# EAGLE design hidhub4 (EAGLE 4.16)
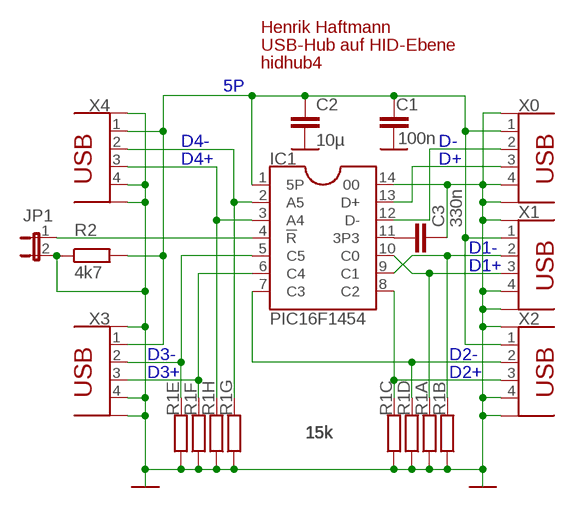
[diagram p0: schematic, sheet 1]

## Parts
C1  100n  C0805  [0805]
C2  10µ  C1206  [1206]
C3  330n  C1206  [1206]
IC1  PIC16F1454  PIC16F1454-I/P  [DIL14]
JP1  JP1E  [JP1]
R1A  15k  R0603  [0603]
R1B  15k  R0603  [0603]
R1C  15k  R0603  [0603]
R1D  15k  R0603  [0603]
R1E  15k  R0603  [0603]
R1F  15k  R0603  [0603]
R1G  15k  R0603  [0603]
R1H  15k  R0603  [0603]
R2  4k7  R0603  [0603]
X0  USBB  [USBB]
X1  USBA  [USBA]
X2  USBA  [USBA]
X3  USBA  [USBA]
X4  USBA  [USBA]

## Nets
3P3: C3.1 IC1.11(3P3)
5P: C1.1 C2.1 IC1.1(5P) R2.2 X0.1(UCC) X1.1(UCC) X2.1(UCC) X3.1(UCC) X4.1(UCC)
D1+: IC1.10(C0) R1A.2 X1.3(D+)
D1-: IC1.9(C1) R1B.2 X1.2(D-)
D2+: IC1.8(C2) R1C.2 X2.3(D+)
D2-: IC1.7(C3) R1D.2 X2.2(D-)
D3+: IC1.6(C4) R1F.2 X3.3(D+)
D3-: IC1.5(C5) R1E.2 X3.2(D-)
D4+: IC1.3(A4) R1H.2 X4.3(D+)
D4-: IC1.2(A5) R1G.2 X4.2(D-)
D+: IC1.13(D+) X0.3(D+)
D-: IC1.12(D-) X0.2(D-)
GND: C1.2 C2.2 C3.2 IC1.14 JP1.2 R1A.1 R1B.1 R1C.1 R1D.1 R1E.1 R1F.1 R1G.1 R1H.1 R2.1 X0.4(GND) X0.S1(S) X0.S2(S) X1.4(GND) X1.S1(S) X1.S2(S) X2.4(GND) X2.S1(S) X2.S2(S) X3.4(GND) X3.S1(S) X3.S2(S) X4.4(GND) X4.S1(S) X4.S2(S)
N$26: IC1.4(!R) JP1.1

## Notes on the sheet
- Henrik Haftmann
- USB-Hub auf HID-Ebene

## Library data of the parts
C1-C3 = fu:C: Kondensator
IC1 = hs-ul:PIC16F145*: 8-bit-Mikrocontroller mit USB Gezeichnet in Gehäuse-Anordnung, für USB-PCS500-Adapter. Typen: PIC16F1454 PIC16F1455 (mit ADU, DAU und 2x Analogvergleicher) Jeweils 8K x 14bit Flash, 1K RAM Features Benötigt keinen Quarz, interne PLL Benötigt keine USB-Serienwiderstände 3,3-V-Spannungsregler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
JP1 = jumper:JP1E: JUMPER
R1A R1B R1C R1D R1E R1F R1G R1H R2 = fu:R: Widerstand
X0 X1-X4 = km:USB: USB-Anschluss Buchse A oder B, mit Schirm

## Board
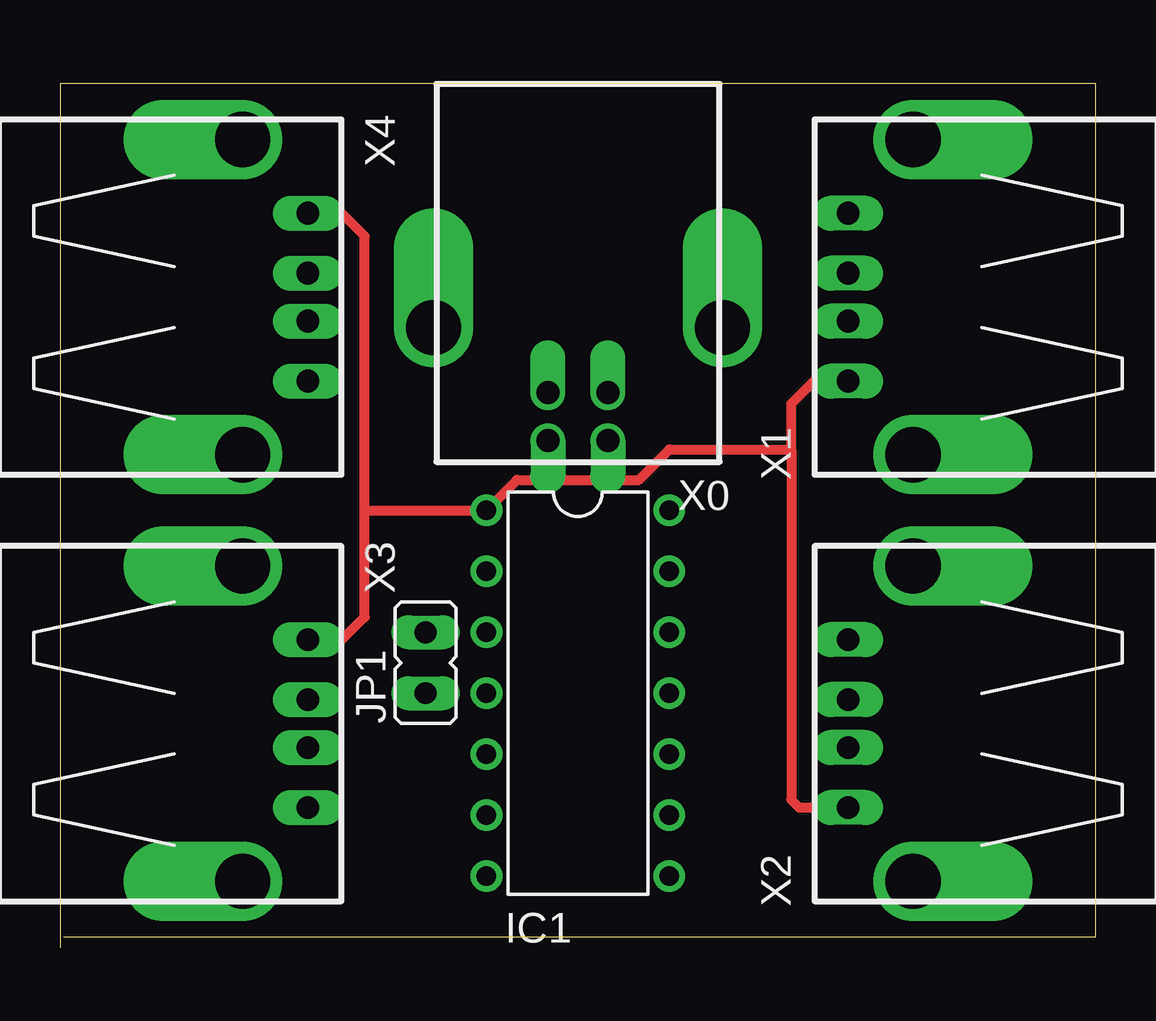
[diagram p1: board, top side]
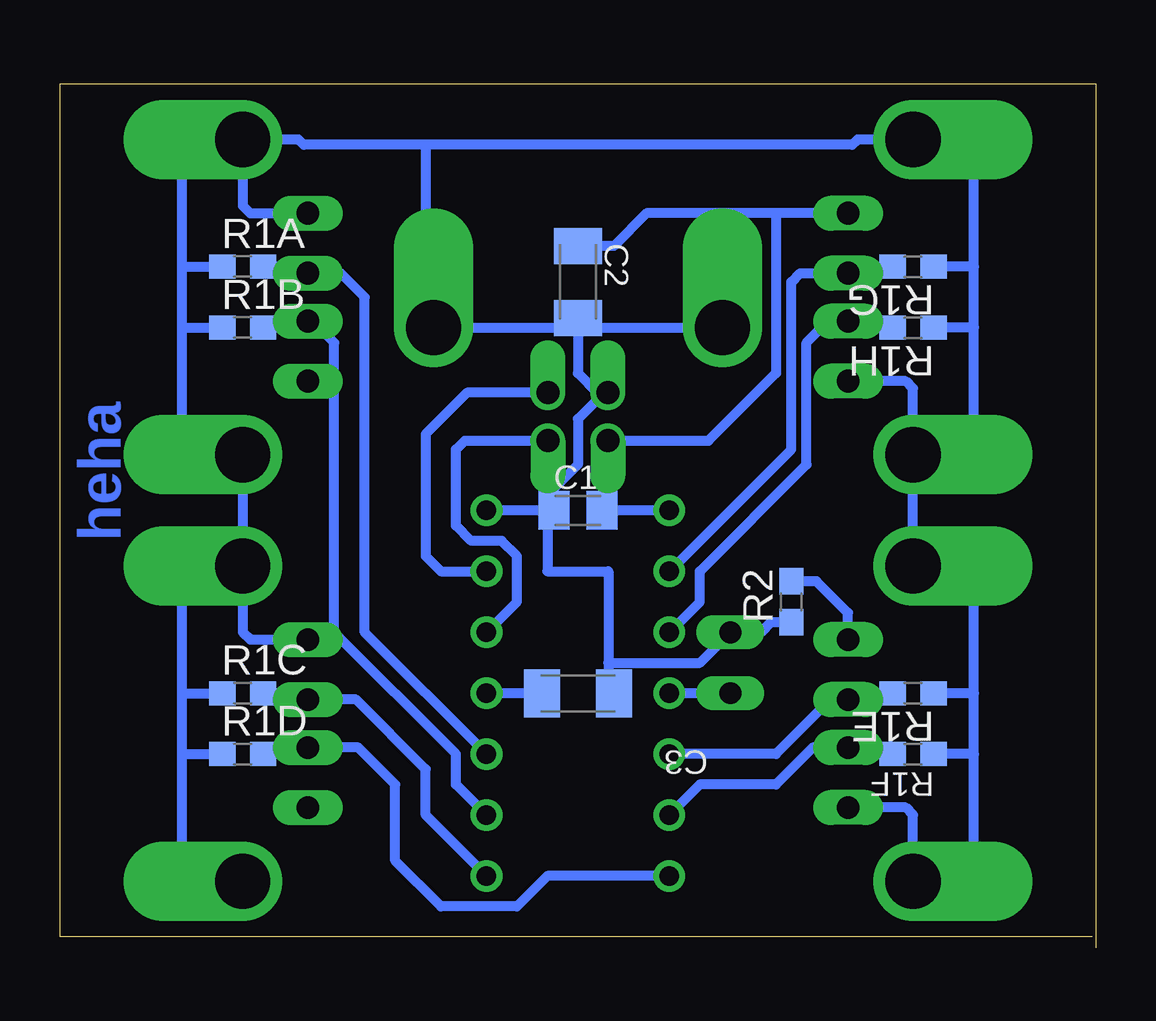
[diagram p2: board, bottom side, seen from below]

Size 43.18 x 36.01 mm. Coordinates in mm from the lower left corner, seen from the top.
Outline: 0.15,0.45 43.18,0.45 43.18,36.01 0,36.01 0,0
Copper layers (1*16): Top 0.035mm / dielectric 1.5mm / Bottom 0.035mm
Design rules "default": minimum track width 0.15mm, minimum drill 0.3mm, track to track 0.15mm, track to pad 0.15mm, pad to pad 0.15mm, via to via 0.15mm, smd to smd 0mil, copper to edge 0.3mm, drill to drill 0.3mm, minimum pad ring 10mil, minimum via ring 8mil, stop-mask expansion 4mil, vias tented up to drill 0mil, thermal gap 10mil

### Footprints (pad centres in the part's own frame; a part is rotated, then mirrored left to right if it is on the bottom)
0805 = smd 1.3 x 1.6: 1 -1,0; 2 1,0
1206 = smd 1.5 x 2: 1 -1.5,0; 2 1.5,0
DIL14 = drill 0.813 pad 1.321 round: 1 -7.62,-3.81; 2 -5.08,-3.81; 3 -2.54,-3.81; 4 0,-3.81; 5 2.54,-3.81; 6 5.08,-3.81; 7 7.62,-3.81; 8 7.62,3.81; 9 5.08,3.81; 10 2.54,3.81; 11 0,3.81; 12 -2.54,3.81; 13 -5.08,3.81; 14 -7.62,3.81
JP1 = drill 0.914 long: 1 0,-1.27; 2 0,1.27
0603 = smd 1.1 x 1: 1 -0.85,0; 2 0.85,0
USBB = drill 0.95 offset: 1 1.25,4.71; 2 -1.25,4.71; 3 -1.25,2.71; 4 1.25,2.71 | drill 2.3 offset: S1 -6.02,0; S2 6.02,0
USBA = drill 0.95 long: 1 -3.5,2.71; 2 -1,2.71; 3 1,2.71; 4 3.5,2.71 | drill 2.3 offset: S1 -6.57,0; S2 6.57,0

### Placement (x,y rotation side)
C1  21.59,18.23 180 bottom
C2  21.59,27.75 270 bottom
C3  21.59,10.61 0 bottom
IC1  21.59,10.61 270 top
JP1  15.24,11.88 0 top
R1A  35.56,28.39 0 bottom
R1B  35.56,25.85 0 bottom
R1C  35.56,10.61 0 bottom
R1D  35.56,8.07 0 bottom
R1E  7.62,10.61 180 bottom
R1F  7.62,8.07 180 bottom
R1G  7.62,28.39 180 bottom
R1H  7.62,25.85 180 bottom
R2  12.7,14.42 90 bottom
X0  21.59,25.85 180 top
X1  35.56,27.12 90 top
X2  35.56,9.34 90 top
X3  7.62,9.34 270 top
X4  7.62,27.12 270 top

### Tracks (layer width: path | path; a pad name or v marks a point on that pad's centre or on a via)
3P3
  Bottom 0.406: C3.1 IC1.11
5P
  Top 0.406: X2.1 30.8,5.84 30.48,6.17 30.48,20.77 | 30.48,20.77 30.48,22.68 31.43,23.62 X1.1 | X4.1 11.74,30.62 12.7,29.66 12.7,18.23 | X3.1 11.76,12.84 12.7,13.79 12.7,18.23 | 12.7,18.23 IC1.1 19.05,19.5 24.13,19.5 25.4,20.77 30.48,20.77
  Bottom 0.406: IC1.1 20.32,18.23 | 20.32,18.23 C1.1 | 20.32,18.23 20.34,18.25 X0.1 16.14,21.14 13.34,23.95 13.34,30.62 | X4.1 13.34,30.62 | 13.34,30.62 18.73,30.62 20.09,29.25 C2.1 | R2.2 11.64,15.27 10.33,13.96 X3.1
D1+
  Bottom 0.406: IC1.10 30.48,13.15 30.48,27.12 31.48,28.12 X1.3 32.85,28.22 33.02,28.39 R1A.2
D1-
  Bottom 0.406: IC1.9 26.67,6.8 26.67,8.07 31.75,13.15 31.75,25.21 32.66,26.12 X1.2 32.85,26.02 33.02,25.85 R1B.2
D2+
  Bottom 0.406: IC1.8 27.94,5.53 27.94,7.44 30.84,10.34 X2.3 32.85,10.44 33.02,10.61 R1C.2
D2-
  Bottom 0.406: IC1.7 22.86,2.99 24.13,1.72 27.3,1.72 29.21,3.62 29.21,6.8 30.75,8.34 X2.2 32.85,8.24 33.02,8.07 R1D.2
D3+
  Bottom 0.406: R1F.2 10.16,8.07 10.33,8.24 X3.3 11.79,8.34 13.34,6.8 16.51,6.8 IC1.6
D3-
  Bottom 0.406: R1E.2 10.16,10.61 10.33,10.44 X3.2 11.06,10.34 13.34,8.07 IC1.5
D4+
  Bottom 0.406: IC1.3 16.51,14.42 16.51,15.69 12.06,20.13 12.06,25.21 11.16,26.12 X4.3 10.33,26.02 10.16,25.85 R1H.2
D4-
  Bottom 0.406: IC1.2 12.7,20.77 12.7,27.75 12.34,28.12 X4.2 10.33,27.93 10.16,27.75 9.53,28.39 R1G.2
D+
  Bottom 0.406: X0.3 26.2,23.14 27.94,21.4 27.94,16.32 27.3,15.69 IC1.13
D-
  Bottom 0.406: X0.2 26.3,21.14 26.67,20.77 26.67,17.59 26.04,16.96 24.77,16.96 24.13,16.32 24.13,14.42 IC1.12
GND
  Bottom 0.406: C3.2 20.32,10.61 20.32,11.88 | 20.32,11.88 20.32,15.69 22.86,15.69 22.86,18.23 | 22.86,18.23 IC1.14 | 20.49,23.14 X0.4 | 20.49,23.14 21.59,22.04 21.59,20.13 22.86,18.86 22.86,18.23 | 22.86,18.23 C1.2 | 21.59,25.85 X0.S2 | 21.59,25.85 X0.S1 27.61,28.06 27.94,28.39 27.94,33.47 | 20.49,23.14 20.79,23.14 21.59,23.95 21.59,25.85 | 21.59,25.85 C2.2 | X2.S1 37.24,2.77 38.1,3.62 38.1,8.07 | 38.1,10.61 38.1,8.07 | X2.S2 37.24,15.91 38.1,15.05 38.1,10.61 | X2.S2 X1.S1 37.24,20.55 38.1,21.4 38.1,25.85 | X1.S2 37.24,33.69 38.1,32.84 38.1,28.39 | 38.1,28.39 38.1,25.85 | X4.S2 5.93,20.55 5.08,21.4 5.08,25.85 | 5.08,25.85 5.08,28.39 | 5.08,28.39 5.08,32.84 5.93,33.69 X4.S1 9.94,33.69 10.16,33.47 27.94,33.47 | 5.08,8.07 5.08,3.62 5.93,2.77 X3.S2 7.62,5.53 7.93,5.84 X3.4 | 5.08,8.07 5.08,10.61 | 5.08,10.61 5.08,15.05 5.93,15.91 X3.S1 X4.S2 | 5.08,8.07 R1F.1 | 5.08,10.61 R1E.1 | 5.08,25.85 R1H.1 | 5.08,28.39 R1G.1 | X4.4 7.93,23.62 7.62,23.31 X4.S2 | X1.4 35.25,30.62 35.56,30.93 X1.S2 | X2.4 35.25,12.84 35.56,13.15 X2.S2 | 38.1,10.61 R1C.1 | 38.1,8.07 R1D.1 | 38.1,25.85 R1B.1 | 38.1,28.39 R1A.1 | 27.94,33.47 33.02,33.47 33.24,33.69 X1.S2 | R2.1 13.55,13.57 13.97,13.15 JP1.2 16.51,11.88 20.32,11.88
N$26
  Bottom 0.406: JP1.1 IC1.4

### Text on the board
Bottom: heha
Document: Lochrasterplatten- | Verdrahtung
